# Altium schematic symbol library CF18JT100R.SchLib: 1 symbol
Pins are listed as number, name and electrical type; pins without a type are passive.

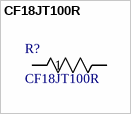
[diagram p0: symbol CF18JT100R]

## CF18JT100R
designator R?
Description; Manufacturer_Name: Stackpole International
footprint STA_CF18_STP
pins: 1, 2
